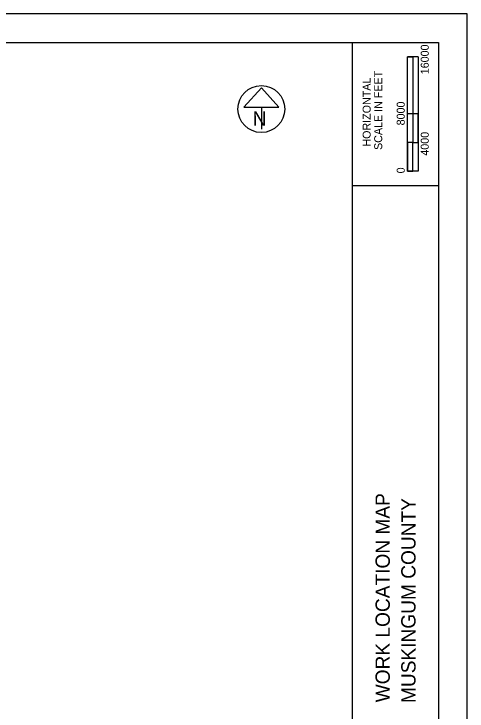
# Model space of a CAD drawing. Extents: x 2015843 to 2287843, y 623733 to 799733.
# Drawn here: x 2224478 to 2287843, y 702171 to 799733 of the extents above; entities that cross this region are included whole.
import ezdxf

# ---------------------------------------------------------------- set-up
doc = ezdxf.new("R2010")
doc.units = 0
for name, color, linetype in [('SH_Border', 7, 'Continuous'), ('SH_Cut_Line', 7, 'Continuous'), ('SH_Data', 7, 'Continuous'), ('SH_Masking', 7, 'Continuous'), ('SH_Text', 7, 'Continuous')]:
    doc.layers.add(name, color=color, linetype=linetype)

msp = doc.modelspace()

# ---------------------------------------------------------------- linework, layer by layer
at = {"layer": 'SH_Border'}
for p, q in [((2271843, 627733), (2271843, 795733)), ((2271843, 775733), (2283843, 775733))]:
    msp.add_line(p, q, dxfattribs=at)
msp.add_lwpolyline([(2027843, 795733), (2283843, 795733), (2283843, 627733), (2027843, 627733)], close=True, dxfattribs=at)
at = {"layer": 'SH_Cut_Line'}
msp.add_lwpolyline([(2015843, 623733), (2287843, 623733), (2287843, 799733), (2015843, 799733)], close=True, dxfattribs=at)
at = {"layer": 'SH_Data'}
for p, q in [((2279496, 777733), (2279496, 793733)), ((2280996, 793733), (2279496, 793733)), ((2279496, 785733), (2279496, 793733)), ((2279496, 793733), (2280243, 793733)), ((2280243, 793733), (2280250, 793733)), ((2280250, 793733), (2280250, 785733)), ((2280996, 793733), (2280996, 777733)), ((2280250, 785733), (2279496, 785733)), ((2280990, 785733), (2280243, 785733)), ((2280243, 785733), (2280243, 781733)), ((2280990, 781733), (2280990, 785733)), ((2280243, 781733), (2279496, 781733)), ((2279496, 781733), (2279496, 777733)), ((2280243, 777733), (2280243, 781733)), ((2280243, 781733), (2280990, 781733)), ((2280996, 777733), (2279496, 777733)), ((2279496, 777733), (2280243, 777733))]:
    msp.add_line(p, q, dxfattribs=at)
at = {"layer": 'SH_Masking'}
msp.add_circle((2259077, 786422), 3280, dxfattribs=at)
at = {"layer": 'SH_Text'}
for p, q in [((2259077, 789412), (2256616, 786682)), ((2261537, 786682), (2259077, 789412)), ((2256616, 786682), (2261537, 786682)), ((2259077, 786682), (2259077, 783588))]:
    msp.add_line(p, q, dxfattribs=at)
msp.add_circle((2259077, 786422), 3280, dxfattribs=at)

# ---------------------------------------------------------------- texts
at = {"layer": 'SH_Data'}
for s, height, p in [('16000', 1120, (2282486, 791292)), ('SCALE IN FEET', 1120, (2275983, 780698)), ('HORIZONTAL', 1120, (2274363, 781167)), ('8000', 1120, (2279127, 784139)), ('4000', 1120, (2282486, 779901)), ('0', 1120, (2279127, 777423)), ('WORK LOCATION MAP', 2000, (2277043, 703391)), ('MUSKINGUM COUNTY', 2000, (2280643, 703299))]:
    msp.add_text(s, height=height, rotation=90, dxfattribs=at).set_placement(p)
at = {"layer": 'SH_Text'}
msp.add_text('N', height=2000, dxfattribs=at).set_placement((2257866, 784091))

doc.saveas('drawing.dxf')
